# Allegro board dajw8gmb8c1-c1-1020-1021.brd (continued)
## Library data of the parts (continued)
D4 D7 D17 D18 D22 PD1 PQ2 PQ8 PQ12-PQ15 PQ18 PQ21 PQ22 PQ25 PQ27 PQ29 PQ33 PQ34 PQ37 PQ41 Q1 Q5-Q9 Q13 Q16 Q18 Q21 Q23 Q26 Q27 Q30 Q33 Q35 Q36 Q38 Q39 Q41-Q43 Q47 Q48 RTCD1 = UMT_213-3-1_3
EL1-EL4 EL6-EL8 = CHOKE-DLP11SN900HL2L-4P-1
EL5 L2 L8 L11 L19-L21 PR9 PR29 PR35 PR53 PR68 PR113 PR118 PR120 PR158 PR175 PR179 = RC0805
EL13 EL14 = CHOKE-NCCM20C900-TR-4P
ESD1-ESD6 PQ3 = TSOP6-2_8-95
EU1-EU3 = UDFN10-2_5X1-5
FAN1 FAN2 = 50271-0040N-V01-4P-L
G1 = SOLDERJUMPER-2
G2 L1 L3 L6 L7 L9 L10 L12-L15 L17 L18 L23-L25 PR3 PR4 PR6 PR10-PR12 PR15-PR21 PR23-PR28 PR31-PR33 PR36 PR37 PR40-PR49 PR52 PR54 PR56-PR59 PR64 PR65 PR67 PR69 PR71 PR74-PR82 PR85-PR87 PR89 PR91 PR93-PR97 PR99-PR102 PR104 PR106-PR112 PR115 PR116 PR119 PR121-PR127 PR129 PR133 PR134 PR136 PR139-PR141 PR143 PR146-PR151 PR159-PR162 PR164 PR166-PR174 PR177 PR180-PR182 PR188 PR190 PR191 PR202-PR207 PR424-PR428 PR432 PR434 R4-R18 R20-R25 R27 R28 R30-R36 R38-R49 R51-R53 R55 R57-R61 R63-R70 R72-R74 R76-R89 R91 R93 R94 R96-R102 R104-R108 R110-R117 R119-R127 R131 R132 R138-R142 R145-R147 R150 R151 R153 R155 R156 R158 R159 R161 R164-R168 R171 R173 R175 R176 R182 R186 R188 R195 R197 R199-R205 R207 R210 R211 R214 R217-R221 R223 R225 R227 R231-R233 R235 R236 R238 R239 R243-R246 R254 R255 R258-R264 R266-R270 R272 R274 R277 R279 R280 R282 R284-R287 R289-R292 R294-R314 R316-R323 R325-R362 R364-R378 R380-R386 R388 R389 R392 R393 R395-R414 R419-R422 R425 R429-R431 R435 R436 R439 R441-R448 R451 R452 R454 R456-R458 R460 R462-R464 R467-R469 R471 R473 R477-R483 R485-R489 R491 R500-R513 R517-R519 R524-R526 R528 RT1 RTCR1 = RC0402
H1 H2 = H-C59D59N
H3 H4 H6 = H-TC236BC315D98P2
H5 = H-TC315BC150D150PT
H7 = H-TC394BC315D130P2
H8 = INTEL-BKT-SHARK-ULT
H9 = H-TC315I190BC150D150PT
H10 H11 H13 = H-TC394BC315D138P2
H12 = H-TSBC315D98P2
H14 = H-TC276BC315D118P2
H17 = H-TC217BC141D141PT
HDMIF1 = F3_2X1_65-2_8
HDMIF2 HDMIF3 = F1_6X0_8-1_8
HE1 Q4 Q25 Q28 Q31 = SOT23_213-3_3-2
JDIM1 = DDR-DDRRK-20401-TP4B-204P-SMT
L4 L5 L32 = CHOKE-WCM2012-4P
L16 L26-L31 PR1 PR34 PR62 PR63 PR72 PR88 PR92 PR98 PR114 PR117 PR128 PR131 PR132 PR135 PR153 PR155 PR184 PR186 PR197-PR200 R1-R3 R37 R273 R453 = RC0603
L22 = L2_5X1_8-1_8-SMT
LED1-LED3 = LEDLTW-C191DS5
PC23-PC25 PC142 PC173 = CC7343-2_15H
PC99 PC141 PC149 PC168 PC172 PC175 = ECAP6D3S
PC100 = ECAP6_3X5_8-7_2
PL1 PL8-PL10 = CHOKE-MPL73-1R5
PL2 = L4_06X4_06-1_8
PL3 PL4 = CHOKE-PCMC063T-R82MN-4P-SMT
PL5 PL6 = CHOKE-ETQP4L
PL7 = CHOKE-MPLC0730L3R3
PQ1 PQ4 PQ7 = POWER-FDMC7678-5P
PQ5 PQ6 PQ16 PQ50 Q3 Q14 Q15 Q17 Q19 Q20 Q24 Q32 Q34 Q37 Q40 Q45 Q46 = SOT-363
PQ9 PQ10 PQ19 Q29 = SSOT6-2_8-95
PQ17 = SOT363-2_1-65-6P
PQ20 PQ23 PQ32 PQ35 PQ42-PQ46 PQ48 PQ49 = PG-TSDSON-8-8P-R
PQ24 PQ26 = SON8-4_5X3_5-5-9P-SMT
PQ28 PQ30 PQ36 PQ38-PQ40 PQ47 = SO-8FL-5P
PQ31 = SC74-2_8-95-6P
PQ901 = SOT23_123-2_37-1_9-1_11H
PR2 PR7 PR13 PR14 PR39 PR50 PR51 PR55 PR60 PR61 PR66 PR70 PR83 PR90 PR105 PR130 PR137 PR138 PR142 PR145 PR152 PR154 PR156 PR163 PR165 PR178 PR189 PR192 PR193 R19 R50 R56 R62 R71 R75 R95 R103 R109 R128 R134 R135 R137 R143 R148 R152 R154 R157 R160 R162 R169 R172 R177 R179 R181 R183 R189 R192 R194 R196 R198 R215 R216 R229 R230 R248 R249 R275 R288 R293 R324 R363 R379 R387 R390 R391 R394 R427 R433 R434 R450 R459 R461 R465 R466 R472 R475 R476 R484 SJ1 SJ2 = SHORT0402
PR8 PR194-PR196 = SHORT0201
PR22 PR103 R240 R283 = RC1206
PR38 = SHORT-1A
PR73 R26 R29 R149 R174 R224 R250 R315 R438 = SHORT0603
PR183 PR201 = RC3216-4P
PU1 PU4 PU5 = QFN24-4X4-5-25P
PU2 = SON8-2X2-5-9P
PU3 = PVQFN20-3_5X3_5-5-25P
PU6 = TQFN20-3X3-4-21P
PU7 = DFN10-3X3-5-11P-RT9296
PU8 = WQFN12-2X2-4-13P-SMT
PU9 = QFN32-4X4-4-42P-1H
PU11 = SOT23-6-4_2-95-6P
Q44 = SC70-2_1-65-6P
R54 R253 R276 R281 R449 R455 = SHORT0805
R440 = SHORT3720
RN1 = 8P4R-0402-SMT
RP1-RP23 = 4P2R-0404
RTCBT1 = 88266-0200-2P-L
TP1-TP9 TP17 TP20-TP29 TP35 TP38 TP40 TP41 TP43-TP54 TP56-TP62 TP64 TP65 TP67-TP70 = TP2650
TP10 TP15 TP16 TP18 TP19 TP30 TP32 TP63 = TP2050
TP11-TP13 TP31 TP33 TP34 TP36 TP37 = TP2675
U1 U15 = SSOP5-P-A-TOSHIBA-B
U2 = QFN40-5X5-4-50P-0_75H
U3 = TSSOP8-4_9-65
U4 U16 U17 = MSOP8-4_9-65
U5 = SOT353-1-2_125-65-5P
U6 U9 = QFN32-4X4-4-33P-0_9H
U7 = QFN40-5X5-4-41P-92HD99
U10 = QFN48-7X7-5-49P-ALC113-GR
U12 = TDFN8-3X3-65-9P-0_85H
U13 = BGA595-NVIDIA-N13P-GV2-S-A2
U14 = BGA1168-INTEL-HASWELL
U18 = QFN16-3X3-5-17P-WM9001
U19 = TRF-9_4-1_27-24P
U21 U24 = SOIC8-7_9-1_27-2_16H
U22 = SOT23-5
U23 = LQFP128-16X16-4
U25 = QFN48-7X7-5-58P-PS8620
VRAM1-VRAM4 = FBGA96-SAMSUNG-K4W2G1646B
Y1 Y4 = XTL-3_2X2_5-2_2X1_7-4P
Y2 = XTL-3_2X2_5-2_2X1_7
Y3 = XTL-3_2X1_5-2_5-0_8H

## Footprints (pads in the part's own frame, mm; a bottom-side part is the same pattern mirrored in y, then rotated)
4P2R-0404
  rect 0.33x0.762 smd: 1(-0.325,-0.5) 2(-0.325,0.5) 3(0.325,-0.5) 4(0.325,0.5)
8P4R-0402-SMT
  rect 0.406x0.61 smd: 1(-0.825,-0.45) 2(-0.825,0.45) 7(0.825,-0.45) 8(0.825,0.45)
  rect 0.254x0.61 smd: 3(-0.25,-0.45) 4(-0.25,0.45) 5(0.25,-0.45) 6(0.25,0.45)
50271-0040N-V01-4P-L
  rect 0.787x1.6 smd: 1(-1.875,2.9) 2(-0.625,2.9) 3(0.625,2.9) 4(1.875,2.9)
  rect 2.108x2.997 smd: 5(-4.425,0) 6(4.425,0)
50281-0060N-001-6P-L-SMT
  rect 0.787x2.007 smd: 1(-3.125,4.05) 2(-1.875,4.05) 3(-0.625,4.05) 4(0.625,4.05) 5(1.875,4.05) 6(3.125,4.05)
  rect 1.499x2.007 smd: 7(-5.075,0) 8(5.075,0)
50456-00841-001-8P-L
  round 1.702 hole 1.702 unplated: (-7.2,0) (7.2,0)
  round 1.346 hole 0.94: 1(-7,3.75) 2(-5,3.75) 3(-3,3.75) 4(-1,3.75) 5(1,3.75) 6(3,3.75) 7(5,3.75) 8(7,3.75)
  rect 1.6x2.489 smd: 9(-10.15,-4.45) 10(10.15,-4.45)
50503-0080N-001-8P-L
  rect 0.508x1.295 smd: 1(-3.5,1.4) 2(-2.5,1.4) 3(-1.5,1.4) 4(-0.5,1.4) 5(0.5,1.4) 6(1.5,1.4) 7(2.5,1.4) 8(3.5,1.4)
  rect 1.803x1.397 smd: 9(-5.65,-1.4) 10(5.65,-1.4)
88266-0200-2P-L
  rect 0.787x2.007 smd: 1(-0.625,2.725) 2(0.625,2.725)
  rect 2.007x2.489 smd: 3(-2.825,-1.325) 4(2.825,-1.325)
88513-0601-6P-L-SMT
  rect 0.508x1.6 smd: 1(-2.5,2.95) 2(-1.5,2.95) 3(-0.5,2.95) 4(0.5,2.95) 5(1.5,2.95) 6(2.5,2.95)
  rect 1.803x1.397 smd: 7(-4.65,0) 8(4.65,0)
BGA595-NVIDIA-N13P-GV2-S-A2
  round 0.381 smd: A2(-9.9,10.7) A3(-9.1,10.7) A4(-8.3,10.7) A6(-6.6,10.7) A7(-5.8,10.7) A9(-4.12,10.7) A10(-3.32,10.7) A12(-1.64,10.7) A13(-0.84,10.7) A15(0.84,10.7) A16(1.64,10.7) A18(3.32,10.7) A19(4.12,10.7) A21(5.8,10.7) A22(6.6,10.7) A24(8.3,10.7) A25(9.1,10.7) A26(9.9,10.7) AA1(-10.7,-5.8) AA2(-9.9,-5.8) AA3(-9.1,-5.8) AA4(-8.3,-5.8) AA5(-7.5,-5.8) AA6(-6.66,-5.8) AA7(-5.8,-5.8) AA8(-4.96,-5.8) AA9(-4.12,-5.86) AA10(-3.32,-5.86) AA12(-1.64,-5.86) AA13(-0.84,-5.86) AA14(0,-5.86) AA15(0.84,-5.86) AA16(1.64,-5.86) AA18(3.32,-5.86) AA19(4.12,-5.86) AA20(4.96,-5.8) AA21(5.8,-5.8) AA22(6.66,-5.8) AA23(7.5,-5.8) AA24(8.3,-5.8) AA25(9.1,-5.8) AA26(9.9,-5.8) AA27(10.7,-5.8) AB1(-10.7,-6.6) AB2(-9.9,-6.6) AB3(-9.1,-6.6) AB4(-8.3,-6.6) AB5(-7.5,-6.6) AB6(-6.6,-6.6) AB7(-5.8,-6.66) AB8(-4.96,-6.66) AB9(-4.12,-6.66) AB10(-3.32,-6.66) AB11(-2.48,-6.66) AB12(-1.64,-6.66) AB13(-0.84,-6.66) AB14(0,-6.66) AB15(0.84,-6.66) AB16(1.64,-6.66) AB17(2.48,-6.66) AB18(3.32,-6.66) AB19(4.12,-6.66) AB20(4.96,-6.66) AB21(5.8,-6.66) AB22(6.6,-6.6) AB23(7.5,-6.6) AB24(8.3,-6.6) AB25(9.1,-6.6) AB26(9.9,-6.6) AB27(10.7,-6.6) AC2(-9.9,-7.45) AC3(-9.1,-7.45) AC4(-8.3,-7.45) AC5(-7.45,-7.45) AC6(-6.6,-7.5) AC7(-5.8,-7.5) AC8(-4.96,-7.5) AC9(-4.12,-7.5) AC10(-3.32,-7.5) AC11(-2.48,-7.5) AC12(-1.64,-7.5) AC13(-0.84,-7.5) AC14(0,-7.5) AC15(0.84,-7.5) AC16(1.64,-7.5) AC17(2.48,-7.5) AC18(3.32,-7.5) AC19(4.12,-7.5) AC20(4.96,-7.5) AC21(5.8,-7.5) AC22(6.6,-7.5) AC23(7.45,-7.45) AC24(8.3,-7.45) AC25(9.1,-7.45) AC26(9.9,-7.45) AD1(-10.7,-8.3) AD2(-9.9,-8.3) AD3(-9.1,-8.3) AD4(-8.3,-8.3) AD5(-7.45,-8.3) AD6(-6.6,-8.3) AD7(-5.8,-8.3) AD8(-4.96,-8.3) AD9(-4.12,-8.3) AD10(-3.32,-8.3) AD11(-2.48,-8.3) AD12(-1.64,-8.3) AD13(-0.84,-8.3) AD14(0,-8.3) AD15(0.84,-8.3) AD16(1.64,-8.3) AD17(2.48,-8.3) AD18(3.32,-8.3) AD19(4.12,-8.3) AD20(4.96,-8.3) AD21(5.8,-8.3) AD22(6.6,-8.3) AD23(7.45,-8.3) AD24(8.3,-8.3) AD25(9.1,-8.3) AD26(9.9,-8.3) AD27(10.7,-8.3) AE1(-10.7,-9.1) AE2(-9.9,-9.1) AE3(-9.1,-9.1) AE4(-8.3,-9.1) AE5(-7.45,-9.1) AE6(-6.6,-9.1) AE7(-5.8,-9.1) AE8(-4.96,-9.1) AE9(-4.12,-9.1) AE10(-3.32,-9.1) AE11(-2.48,-9.1) AE12(-1.64,-9.1) AE13(-0.84,-9.1) AE14(0,-9.1) AE15(0.84,-9.1) AE16(1.64,-9.1) AE17(2.48,-9.1) AE18(3.32,-9.1) AE19(4.12,-9.1) AE20(4.96,-9.1) AE21(5.8,-9.1) AE22(6.6,-9.1) AE23(7.45,-9.1) AE24(8.3,-9.1) AE25(9.1,-9.1) AE26(9.9,-9.1) AE27(10.7,-9.1) AF1(-10.7,-9.9) AF2(-9.9,-9.9) AF3(-9.1,-9.9) AF4(-8.3,-9.9) AF5(-7.45,-9.9) AF6(-6.6,-9.9) AF7(-5.8,-9.9) AF8(-4.96,-9.9) AF9(-4.12,-9.9) AF10(-3.32,-9.9) AF11(-2.48,-9.9) AF12(-1.64,-9.9) AF13(-0.84,-9.9) AF14(0,-9.9) AF15(0.84,-9.9) AF16(1.64,-9.9) AF17(2.48,-9.9) AF18(3.32,-9.9) AF19(4.12,-9.9) AF20(4.96,-9.9) AF21(5.8,-9.9) AF22(6.6,-9.9) AF23(7.45,-9.9) AF24(8.3,-9.9) AF25(9.1,-9.9) AF26(9.9,-9.9) AF27(10.7,-9.9) AG2(-9.9,-10.7) AG3(-9.1,-10.7) AG4(-8.3,-10.7) AG6(-6.6,-10.7) AG7(-5.8,-10.7) AG9(-4.12,-10.7) AG10(-3.32,-10.7) AG12(-1.64,-10.7) AG13(-0.84,-10.7) AG15(0.84,-10.7) AG16(1.64,-10.7) AG18(3.32,-10.7) AG19(4.12,-10.7) AG21(5.8,-10.7) AG22(6.6,-10.7) AG24(8.3,-10.7) AG25(9.1,-10.7) AG26(9.9,-10.7) B1(-10.7,9.9) B2(-9.9,9.9) B3(-9.1,9.9) B4(-8.3,9.9) B5(-7.45,9.9) B6(-6.6,9.9) B7(-5.8,9.9) B8(-4.96,9.9) B9(-4.12,9.9) B10(-3.32,9.9) B11(-2.48,9.9) B12(-1.64,9.9) B13(-0.84,9.9) B14(0,9.9) B15(0.84,9.9) B16(1.64,9.9) B17(2.48,9.9) B18(3.32,9.9) B19(4.12,9.9) B20(4.96,9.9) B21(5.8,9.9) B22(6.6,9.9) B23(7.45,9.9) B24(8.3,9.9) B25(9.1,9.9) B26(9.9,9.9) B27(10.7,9.9) C1(-10.7,9.1) C2(-9.9,9.1) C3(-9.1,9.1) C4(-8.3,9.1) C5(-7.45,9.1) C6(-6.6,9.1) C7(-5.8,9.1) C8(-4.96,9.1) C9(-4.12,9.1) C10(-3.32,9.1) C11(-2.48,9.1) C12(-1.64,9.1) C13(-0.84,9.1) C14(0,9.1) C15(0.84,9.1) C16(1.64,9.1) C17(2.48,9.1) C18(3.32,9.1) C19(4.12,9.1) C20(4.96,9.1) C21(5.8,9.1) C22(6.6,9.1) C23(7.45,9.1) C24(8.3,9.1) C25(9.1,9.1) C26(9.9,9.1) C27(10.7,9.1) D1(-10.7,8.3) D2(-9.9,8.3) D3(-9.1,8.3) D4(-8.3,8.3) D5(-7.45,8.3) D6(-6.6,8.3) D7(-5.8,8.3) D8(-4.96,8.3) D9(-4.12,8.3) D10(-3.32,8.3) D11(-2.48,8.3) D12(-1.64,8.3) D13(-0.84,8.3) D14(0,8.3) D15(0.84,8.3) D16(1.64,8.3) D17(2.48,8.3) D18(3.32,8.3) D19(4.12,8.3) D20(4.96,8.3) D21(5.8,8.3) D22(6.6,8.3) D23(7.45,8.3) D24(8.3,8.3) D25(9.1,8.3) D26(9.9,8.3) D27(10.7,8.3) E2(-9.9,7.45) E3(-9.1,7.45) E4(-8.3,7.45) E5(-7.45,7.45) E6(-6.6,7.5) E7(-5.8,7.5) E8(-4.96,7.5) E9(-4.12,7.5) E10(-3.32,7.5) E11(-2.48,7.5) E12(-1.64,7.5) E13(-0.84,7.5) E14(0,7.5) E15(0.84,7.5) E16(1.64,7.5) E17(2.48,7.5) E18(3.32,7.5) E19(4.12,7.5) E20(4.96,7.5) E21(5.8,7.5) E22(6.6,7.5) E23(7.45,7.45) E24(8.3,7.45) E25(9.1,7.45) E26(9.9,7.45) F1(-10.7,6.6) F2(-9.9,6.6) F3(-9.1,6.6) F4(-8.3,6.6) F5(-7.5,6.6) F6(-6.6,6.6) F7(-5.8,6.66) F8(-4.96,6.66) F9(-4.12,6.66) F10(-3.32,6.66) F11(-2.48,6.66) F12(-1.64,6.66) F13(-0.84,6.66) F14(0,6.66) F15(0.84,6.66) F16(1.64,6.66) F17(2.48,6.66) F18(3.32,6.66) F19(4.12,6.66) F20(4.96,6.66) F21(5.8,6.66) F22(6.6,6.6) F23(7.5,6.6) F24(8.3,6.6) F25(9.1,6.6) F26(9.9,6.6) F27(10.7,6.6) G1(-10.7,5.8) G2(-9.9,5.8) G3(-9.1,5.8) G4(-8.3,5.8) G5(-7.5,5.8) G6(-6.66,5.8) G7(-5.8,5.8) G8(-4.96,5.8) G9(-4.12,5.86) G10(-3.32,5.86) G12(-1.64,5.86) G13(-0.84,5.86) G14(0,5.86) G15(0.84,5.86) G16(1.64,5.86) G18(3.32,5.86) G19(4.12,5.86) G20(4.96,5.8) G21(5.8,5.8) G22(6.66,5.8) G23(7.5,5.8) G24(8.3,5.8) G25(9.1,5.8) G26(9.9,5.8) G27(10.7,5.8) H2(-9.9,4.96) H3(-9.1,4.96) H4(-8.3,4.96) H5(-7.5,4.96) H6(-6.66,4.96) H22(6.66,4.96) H23(7.5,4.96) H24(8.3,4.96) H25(9.1,4.96) H26(9.9,4.96) J1(-10.7,4.12) J2(-9.9,4.12) J3(-9.1,4.12) J4(-8.3,4.12) J5(-7.5,4.12) J6(-6.66,4.12) J7(-5.86,4.12) J21(5.86,4.12) J22(6.66,4.12) J23(7.5,4.12) J24(8.3,4.12) J25(9.1,4.12) J26(9.9,4.12) J27(10.7,4.12) K1(-10.7,3.32) K2(-9.9,3.32) K3(-9.1,3.32) K4(-8.3,3.32) K5(-7.5,3.32) K6(-6.66,3.32) K7(-5.86,3.32) K21(5.86,3.32) K22(6.66,3.32) K23(7.5,3.32) K24(8.3,3.32) K25(9.1,3.32) K26(9.9,3.32) K27(10.7,3.32) L2(-9.9,2.48) L3(-9.1,2.48) L4(-8.3,2.48) L5(-7.5,2.48) L6(-6.66,2.48) L22(6.66,2.48) L23(7.5,2.48) L24(8.3,2.48) L25(9.1,2.48) L26(9.9,2.48) M1(-10.7,1.64) M2(-9.9,1.64) M3(-9.1,1.64) M4(-8.3,1.64) M5(-7.5,1.64) M6(-6.66,1.64) M7(-5.86,1.64) M21(5.86,1.64) M22(6.66,1.64) M23(7.5,1.64) M24(8.3,1.64) M25(9.1,1.64) M26(9.9,1.64) M27(10.7,1.64) N1(-10.7,0.84) N2(-9.9,0.84) N3(-9.1,0.84) N4(-8.3,0.84) N5(-7.5,0.84) N6(-6.66,0.84) N7(-5.86,0.84) N21(5.86,0.84) N22(6.66,0.84) N23(7.5,0.84) N24(8.3,0.84) N25(9.1,0.84) N26(9.9,0.84) N27(10.7,0.84) P2(-9.9,0) P3(-9.1,0) P4(-8.3,0) P5(-7.5,0) P6(-6.66,0) P22(6.66,0) P23(7.5,0) P24(8.3,0) P25(9.1,0) P26(9.9,0) R1(-10.7,-0.84) R2(-9.9,-0.84) R3(-9.1,-0.84) R4(-8.3,-0.84) R5(-7.5,-0.84) R6(-6.66,-0.84) R7(-5.86,-0.84) R21(5.86,-0.84) R22(6.66,-0.84) R23(7.5,-0.84) R24(8.3,-0.84) R25(9.1,-0.84) R26(9.9,-0.84) R27(10.7,-0.84) T1(-10.7,-1.64) T2(-9.9,-1.64) T3(-9.1,-1.64) T4(-8.3,-1.64) T5(-7.5,-1.64) T6(-6.66,-1.64) T7(-5.86,-1.64) T21(5.86,-1.64) T22(6.66,-1.64) T23(7.5,-1.64) T24(8.3,-1.64) T25(9.1,-1.64) T26(9.9,-1.64) T27(10.7,-1.64) U2(-9.9,-2.48) U3(-9.1,-2.48) U4(-8.3,-2.48) U5(-7.5,-2.48) U6(-6.66,-2.48) U22(6.66,-2.48) U23(7.5,-2.48) U24(8.3,-2.48) U25(9.1,-2.48) U26(9.9,-2.48) V1(-10.7,-3.32) V2(-9.9,-3.32) V3(-9.1,-3.32) V4(-8.3,-3.32) V5(-7.5,-3.32) V6(-6.66,-3.32) V7(-5.86,-3.32) V21(5.86,-3.32) V22(6.66,-3.32) V23(7.5,-3.32) V24(8.3,-3.32) V25(9.1,-3.32) V26(9.9,-3.32) V27(10.7,-3.32) W1(-10.7,-4.12) W2(-9.9,-4.12) W3(-9.1,-4.12) W4(-8.3,-4.12) W5(-7.5,-4.12) W6(-6.66,-4.12) W7(-5.86,-4.12) W21(5.86,-4.12) W22(6.66,-4.12) W23(7.5,-4.12) W24(8.3,-4.12) W25(9.1,-4.12) W26(9.9,-4.12) W27(10.7,-4.12) Y2(-9.9,-4.96) Y3(-9.1,-4.96) Y4(-8.3,-4.96) Y5(-7.5,-4.96) Y6(-6.66,-4.96) Y22(6.66,-4.96) Y23(7.5,-4.96) Y24(8.3,-4.96) Y25(9.1,-4.96) Y26(9.9,-4.96)
  round 0.4 smd: K10(-4,4) K11(-3,4) K12(-2,4) K13(-1,4) K14(0,4) K15(1,4) K16(2,4) K17(3,4) K18(4,4) L10(-4,3) L11(-3,3) L12(-2,3) L13(-1,3) L14(0,3) L15(1,3) L16(2,3) L17(3,3) L18(4,3) M10(-4,2) M11(-3,2) M12(-2,2) M13(-1,2) M14(0,2) M15(1,2) M16(2,2) M17(3,2) M18(4,2) N10(-4,1) N11(-3,1) N12(-2,1) N13(-1,1) N14(0,1) N15(1,1) N16(2,1) N17(3,1) N18(4,1) P10(-4,0) P11(-3,0) P12(-2,0) P13(-1,0) P14(0,0) P15(1,0) P16(2,0) P17(3,0) P18(4,0) R10(-4,-1) R11(-3,-1) R12(-2,-1) R13(-1,-1) R14(0,-1) R15(1,-1) R16(2,-1) R17(3,-1) R18(4,-1) T10(-4,-2) T11(-3,-2) T12(-2,-2) T13(-1,-2) T14(0,-2) T15(1,-2) T16(2,-2) T17(3,-2) T18(4,-2) U10(-4,-3) U11(-3,-3) U12(-2,-3) U13(-1,-3) U14(0,-3) U15(1,-3) U16(2,-3) U17(3,-3) U18(4,-3) V10(-4,-4) V11(-3,-4) V12(-2,-4) V13(-1,-4) V14(0,-4) V15(1,-4) V16(2,-4) V17(3,-4) V18(4,-4)
BGA1168-INTEL-HASWELL
  round 0.508 smd: A3(18.177,-11.314) A62(-18.722,-11.314) AW1(19.314,10.727) AW63(-19.314,10.743) AY2(18.771,11.314) AY62(-18.748,11.314) B2(18.806,-10.806) B63(-19.314,-10.722) C1(19.314,-10.177)
  round 0.381 smd: A4(17.421,-11.314) A5(16.76,-11.314) A6(15.564,-11.314) A59(-16.586,-11.314) A60(-17.412,-11.314) A61(-18.072,-11.314) AA9(14.282,0.262) AA21(7.627,0.175) AA23(6.199,0.175) AA58(-16.063,0.015) AB10(13.838,0.738) AB20(8.135,0.582) AB21(7.627,0.988) AB22(6.707,0.582) AB23(6.199,0.988) AB57(-15.743,0.666) AC9(14.282,1.215) AC20(8.135,1.394) AC22(6.707,1.394) AC58(-16.063,1.316) AD10(13.838,1.691) AD21(7.627,1.801) AD23(6.199,1.801) AD57(-15.743,1.966) AE9(14.282,2.167) AE10(13.838,2.643) AE20(8.135,2.207) AE21(7.627,2.614) AE22(6.707,2.207) AE23(6.199,2.614) AE58(-16.063,2.616) AF9(14.282,3.12) AF11(13.255,2.968) AF12(12.442,2.968) AF14(11.63,2.968) AF15(10.817,2.968) AF17(10.004,2.968) AF18(9.191,2.968) AF20(8.378,2.968) AF22(6.707,3.02) AG10(13.662,3.476) AG11(12.849,3.476) AG13(12.036,3.476) AG14(11.223,3.476) AG16(10.41,3.476) AG17(9.598,3.476) AG19(8.785,3.476) AG20(7.972,3.476) AG23(6.199,3.426) AG57(-15.743,3.267) AG58(-16.377,3.695) AH22(6.707,3.833) AH24(5.394,3.975) AH26(4.094,3.975) AH28(2.793,3.975) AH30(1.493,3.975) AH32(0.192,3.975) AH34(-1.108,3.975) AH36(-2.409,3.975) AH38(-3.709,3.975) AH40(-5.01,3.975) AH42(-6.31,3.975) AH44(-7.611,3.975) AH46(-8.911,3.975) AH49(-10.212,3.975) AH51(-11.512,3.975) AH53(-12.813,3.975) AH55(-14.113,3.975) AH57(-15.413,3.975) AJ23(6.199,4.239) AJ25(4.744,4.3) AJ27(3.443,4.3) AJ29(2.143,4.3) AJ31(0.843,4.3) AJ33(-0.458,4.3) AJ35(-1.758,4.3) AJ37(-3.059,4.3) AJ39(-4.359,4.3) AJ41(-5.66,4.3) AJ43(-6.96,4.3) AJ45(-8.261,4.3) AJ47(-9.561,4.3) AJ50(-10.862,4.3) AJ52(-12.162,4.3) AJ54(-13.463,4.3) AJ56(-14.763,4.3) AJ58(-16.064,4.3) AT1(19.314,8.683) AT63(-19.314,8.533) AU1(19.314,9.343) AU63(-19.314,9.359) AV1(19.314,10.004) AV2(18.654,9.993) AV62(-18.664,10.004) AV63(-19.314,10.019) AW2(18.654,10.654) AW3(17.993,10.654) AW61(-18.014,10.664) AW62(-18.664,10.664) AY3(18.047,11.314) AY4(17.387,11.314) AY5(16.726,11.314) AY59(-16.774,11.314) AY60(-17.434,11.314) AY61(-18.095,11.314) B3(18.056,-10.664) B61(-18.001,-10.654) B62(-18.664,-10.59) C2(18.664,-10.056) C62(-18.664,-9.93) C63(-19.314,-9.998) D1(19.314,-9.453) D63(-19.314,-9.338) E1(19.314,-8.792) E23(5.981,-8.713) E25(4.6,-8.713) E27(3.474,-8.713) E29(2.093,-8.713) E31(0.966,-8.713) E33(-0.415,-8.713) E35(-1.541,-8.713) E37(-2.922,-8.713) E39(-4.049,-8.713) E41(-5.43,-8.713) E43(-6.556,-8.713) E45(-7.937,-8.713) E47(-9.064,-8.713) E49(-10.444,-8.713) E51(-11.571,-8.713) E53(-12.952,-8.713) E55(-14.079,-8.713) E57(-15.459,-8.713) E63(-19.314,-8.667) F1(19.314,-7.878) F22(6.597,-8.256) F24(5.291,-8.188) F26(4.037,-8.188) F28(2.783,-8.188) F30(1.53,-8.188) F32(0.276,-8.188) F34(-0.978,-8.188) F36(-2.232,-8.188) F38(-3.485,-8.188) F40(-4.739,-8.188) F42(-5.993,-8.188) F44(-7.247,-8.188) F46(-8.5,-8.188) F48(-9.754,-8.188) F50(-11.008,-8.188) F52(-12.262,-8.188) F54(-13.515,-8.188) F56(-14.769,-8.188) F58(-16.063,-8.188) G22(6.707,-7.546) G23(5.981,-7.863) G25(4.6,-7.863) G27(3.474,-7.863) G29(2.093,-7.863) G31(0.966,-7.863) G33(-0.415,-7.863) G35(-1.541,-7.863) G37(-2.922,-7.863) G39(-4.049,-7.863) G41(-5.43,-7.863) G43(-6.556,-7.863) G45(-7.937,-7.863) G47(-9.064,-7.863) G49(-10.444,-7.863) G51(-11.571,-7.863) G53(-12.952,-7.863) G55(-14.079,-7.863) G57(-15.459,-7.863) H22(6.707,-6.734) H23(6.199,-7.14) H57(-15.743,-7.213) J22(6.707,-5.921) J23(6.199,-6.327) J58(-16.063,-6.487) K9(14.282,-5.453) K10(13.379,-5.614) K12(12.426,-5.614) K14(11.474,-5.614) K16(10.521,-5.614) K18(9.569,-5.614) K19(8.616,-5.614) K21(7.664,-5.614) K23(6.199,-5.514) K57(-15.743,-5.837) L10(13.838,-4.977) L11(12.902,-5.17) L13(11.95,-5.17) L15(10.997,-5.17) L17(10.045,-5.17) L18(9.092,-5.17) L20(8.135,-5.108) L22(6.707,-5.108) L58(-16.063,-5.186) M9(14.282,-4.5) M20(8.135,-4.295) M21(7.627,-4.702) M22(6.707,-4.295) M23(6.199,-4.702) M57(-15.743,-4.536) N10(13.838,-4.024) N21(7.627,-3.889) N23(6.199,-3.889) N58(-16.063,-3.886) P9(14.282,-3.548) P20(8.135,-3.482) P22(6.707,-3.482) P57(-15.743,-3.236) R10(13.838,-3.072) R20(8.135,-2.67) R21(7.627,-3.076) R22(6.707,-2.67) R23(6.199,-3.076) T9(14.282,-2.595) T21(7.627,-2.263) T23(6.199,-2.263) T58(-16.063,-2.585) U9(14.282,-1.643) U10(13.838,-2.119) U20(8.135,-1.857) U22(6.707,-1.857) U57(-15.743,-1.935) V10(13.838,-1.167) V21(7.627,-1.45) V23(6.199,-1.45) V58(-16.063,-1.285) W9(14.282,-0.69) W20(8.135,-1.044) W21(7.627,-0.638) W22(6.707,-1.044) W23(6.199,-0.638) W57(-15.743,-0.635) Y10(13.838,-0.214) Y20(8.135,-0.231) Y22(6.707,-0.231)
  round 0.305 smd: A8(14.776,-11.314) A9(13.862,-11.314) A11(12.948,-11.314) A12(12.198,-11.314) A14(11.284,-11.314) A15(10.37,-11.314) A17(9.62,-11.314) A18(8.706,-11.314) A20(7.791,-11.314) A21(7.042,-11.314) A23(6.128,-11.314) A24(5.291,-10.989) A25(4.6,-11.314) A27(3.474,-11.314) A28(2.783,-10.989) A29(2.093,-11.314) A31(0.966,-11.314) A32(0.276,-10.989) A33(-0.415,-11.314) A35(-1.541,-11.314) A36(-2.232,-10.989) A37(-2.922,-11.314) A39(-4.049,-11.314) A40(-4.739,-10.989) A41(-5.43,-11.314) A43(-6.556,-11.314) A44(-7.247,-10.989) A45(-7.937,-11.314) A47(-9.064,-11.314) A48(-9.754,-10.989) A49(-10.444,-11.314) A51(-11.571,-11.314) A52(-12.262,-10.989) A53(-12.952,-11.314) A55(-14.079,-11.314) A56(-14.769,-10.989) A57(-15.459,-11.314) AA1(19.314,0.402) AA2(18.664,0.402) AA3(18.014,0.364) AA4(17.363,0.364) AA59(-16.713,0.324) AA60(-17.363,0.324) AA61(-18.014,0.324) AA62(-18.664,0.362) AA63(-19.314,0.362) AB5(16.678,0.738) AB6(16.027,0.738) AB7(15.377,0.738) AB8(14.727,0.738) AC1(19.314,1.152) AC2(18.664,1.152) AC3(18.014,1.19) AC4(17.363,1.19) AC59(-16.713,1.15) AC60(-17.363,1.15) AC61(-18.014,1.15) AC62(-18.664,1.112) AC63(-19.314,1.112) AD1(19.314,1.901) AD2(18.664,1.901) AD3(18.014,1.863) AD4(17.363,1.863) AD5(16.678,1.691) AD6(16.027,1.691) AD7(15.377,1.691) AD8(14.727,1.691) AD59(-16.713,1.823) AD60(-17.363,1.823) AD61(-18.014,1.823) AD62(-18.664,1.861) AD63(-19.314,1.861) AE5(16.678,2.643) AE6(16.027,2.643) AE7(15.377,2.643) AE8(14.727,2.643) AE59(-16.713,2.648) AE60(-17.363,2.648) AE61(-18.014,2.648) AE62(-18.664,2.61) AE63(-19.314,2.61) AF1(19.314,2.65) AF2(18.664,2.65) AF3(18.014,2.688) AF4(17.363,2.688) AG1(19.314,3.4) AG2(18.664,3.4) AG3(18.014,3.361) AG4(17.363,3.361) AG5(16.678,3.596) AG6(16.027,3.596) AG7(15.377,3.596) AG8(14.727,3.596) AG21(7.359,3.807) AG60(-17.038,3.288) AG61(-17.689,3.288) AG62(-18.339,3.288) AG63(-18.989,3.288) AH1(19.314,4.149) AH2(18.664,4.149) AH3(18.014,4.187) AH4(17.363,4.187) AH10(13.662,4.162) AH11(12.849,4.162) AH13(12.036,4.162) AH14(11.223,4.162) AH16(10.41,4.162) AH17(9.598,4.162) AH19(8.785,4.162) AH20(7.972,4.162) AH60(-17.363,3.964) AH61(-18.014,3.964) AH62(-18.664,3.964) AH63(-19.314,3.964) AJ5(16.678,4.548) AJ6(16.027,4.548) AJ7(15.377,4.548) AJ8(14.727,4.548) AJ10(13.662,4.812) AJ11(12.849,4.812) AJ13(12.036,4.812) AJ14(11.223,4.812) AJ60(-17.038,4.64) AJ61(-17.689,4.64) AJ62(-18.339,4.64) AJ63(-18.989,4.64) AK1(19.314,4.898) AK2(18.664,4.898) AK3(18.014,4.86) AK4(17.363,4.86) AK8(15.011,5.137) AK18(9.466,4.952) AK20(8.513,4.952) AK21(7.561,4.952) AK60(-17.363,5.209) AK61(-18.014,5.209) AK62(-18.664,5.315) AK63(-19.314,5.315) AL1(19.314,5.647) AL2(18.664,5.647) AL3(18.014,5.686) AL4(17.363,5.686) AL5(16.413,5.462) AL7(15.575,5.462) AL8(15.011,5.787) AL10(13.657,5.462) AL11(13.093,5.787) AL13(11.738,5.462) AL15(11.174,5.787) AL17(10.092,5.268) AL18(9.466,5.602) AL20(8.513,5.602) AL21(7.561,5.602) AL22(6.608,5.602) AL23(5.786,5.602) AL25(4.81,5.602) AL26(3.858,5.602) AL28(2.905,5.602) AL29(1.953,5.602) AL31(1.054,5.277) AL32(0.49,5.602) AL33(-0.412,5.602) AL35(-1.415,5.602) AL36(-2.266,5.602) AL38(-3.32,5.602) AL39(-4.228,5.277) AL40(-4.817,5.602) AL42(-5.63,5.602) AL43(-6.582,5.602) AL45(-7.56,5.602) AL46(-8.487,5.602) AL48(-9.542,5.602) AL49(-10.443,5.602) AL51(-11.447,5.602) AL52(-12.269,5.602) AL54(-13.295,5.602) AL55(-14.248,5.602) AL57(-15.195,5.602) AL58(-16.094,5.602) AL60(-17.038,5.855) AL61(-17.689,5.855) AM1(19.314,6.397) AM2(18.664,6.397) AM3(18.014,6.359) AM4(17.363,6.359) AM5(16.413,6.112) AM7(15.575,6.112) AM8(15.011,6.437) AM10(13.657,6.112) AM11(13.093,6.437) AM13(11.738,6.112) AM15(11.174,6.437) AM17(10.092,5.919) AM18(9.466,6.252) AM20(8.513,6.252) AM21(7.561,6.252) AM22(6.608,6.252) AM23(5.786,6.252) AM25(4.81,6.252) AM26(3.858,6.252) AM28(2.905,6.252) AM29(1.953,6.252) AM31(1.054,5.927) AM32(0.49,6.252) AM33(-0.412,6.252) AM35(-1.415,6.252) AM36(-2.266,6.252) AM38(-3.32,6.252) AM40(-4.817,6.252) AM42(-5.63,6.252) AM43(-6.582,6.252) AM45(-7.56,6.252) AM46(-8.487,6.252) AM48(-9.542,6.252) AM49(-10.443,6.252) AM51(-11.447,6.252) AM52(-12.269,6.252) AM54(-13.295,6.252) AM55(-14.248,6.252) AM57(-15.195,6.252) AM58(-16.094,6.252) AM60(-17.363,6.501) AM61(-18.014,6.501) AM62(-18.664,6.395) AM63(-19.314,6.395) AN1(19.314,7.146) AN2(18.664,7.146) AN3(18.014,7.184) AN4(17.363,7.184) AN5(16.413,6.762) AN7(15.575,6.762) AN8(15.011,7.088) AN10(13.657,6.762) AN11(13.093,7.088) AN13(11.738,6.762) AN15(11.174,7.088) AN17(10.092,6.569) AN18(9.466,6.903) AN20(8.513,6.903) AN21(7.561,6.903) AN22(6.608,6.903) AN23(5.786,6.903) AN25(4.81,6.903) AN26(3.858,6.903) AN28(2.905,6.903) AN29(1.953,6.903) AN31(1.054,6.578) AN32(0.49,6.903) AN33(-0.412,6.903) AN35(-1.415,6.903) AN36(-2.266,6.903) AN38(-3.32,6.903) AN39(-4.228,6.578) AN40(-4.817,6.903) AN42(-5.63,6.903) AN43(-6.582,6.903) AN45(-7.56,6.903) AN46(-8.487,6.903) AN48(-9.542,6.903) AN49(-10.443,6.903) AN51(-11.447,6.903) AN52(-12.269,6.903) AN54(-13.295,6.903) AN55(-14.248,6.903) AN57(-15.195,6.903) AN58(-16.094,6.903) AN60(-17.038,7.07) AN61(-17.689,7.07) AN62(-18.339,7.07) AN63(-18.989,7.07) AP1(19.314,7.895) AP2(18.664,7.895) AP3(18.014,7.857) AP4(17.363,7.857) AP5(16.413,7.413) AP7(15.575,7.413) AP8(15.011,7.738) AP10(13.657,7.413) AP11(13.093,7.738) AP13(11.738,7.413) AP15(11.174,7.738) AP17(10.092,7.219) AP18(9.466,7.553) AP20(8.513,7.553) AP21(7.561,7.553) AP22(6.608,7.553) AP23(5.786,7.553) AP25(4.81,7.553) AP26(3.858,7.553) AP28(2.905,7.553) AP29(1.953,7.553) AP31(1.054,7.228) AP32(0.49,7.553) AP33(-0.412,7.553) AP35(-1.415,7.553) AP36(-2.266,7.553) AP38(-3.32,7.553) AP39(-4.228,7.228) AP40(-4.817,7.553) AP42(-5.63,7.553) AP43(-6.582,7.553) AP45(-7.56,7.553) AP46(-8.487,7.553) AP48(-9.542,7.553) AP49(-10.443,7.553) AP51(-11.447,7.553) AP52(-12.269,7.553) AP54(-13.295,7.553) AP55(-14.248,7.553) AP57(-15.195,7.553) AP58(-16.094,7.553) AP60(-17.363,7.746) AP61(-18.014,7.746) AP62(-18.664,7.746) AP63(-19.314,7.746) AR5(16.413,8.063) AR7(15.575,8.063) AR8(15.011,8.388) AR10(13.657,8.063) AR11(13.093,8.388) AR13(11.738,8.063) AR15(11.174,8.388) AR17(10.092,7.869) AR18(9.466,8.203) AR20(8.513,8.203) AR21(7.561,8.203) AR22(6.608,8.203) AR23(5.786,8.203) AR25(4.81,8.203) AR26(3.858,8.203) AR28(2.905,8.203) AR29(1.953,8.203) AR31(1.054,7.878) AR32(0.49,8.203) AR33(-0.412,8.203) AR35(-1.415,8.203) AR36(-2.266,8.203) AR38(-3.32,8.203) AR39(-4.228,7.878) AR40(-4.817,8.203) AR42(-5.63,8.203) AR43(-6.582,8.203) AR45(-7.56,8.203) AR46(-8.487,8.203) AR48(-9.542,8.203) AR49(-10.443,8.203) AR51(-11.447,8.203) AR52(-12.269,8.203) AR54(-13.295,8.203) AR55(-14.248,8.203) AR57(-15.195,8.203) AR58(-16.094,8.203) AT2(18.664,8.645) AT3(18.014,8.683) AT4(17.363,8.683) AT5(16.413,8.713) AT7(15.575,8.713) AT10(13.657,8.713) AT13(11.738,8.713) AT35(-1.122,8.905) AT37(-2.697,8.905) AT40(-4.272,8.905) AT42(-5.847,8.905) AT43(-7.422,8.905) AT46(-8.996,8.905) AT49(-10.597,8.933) AT61(-17.689,8.32) AT62(-18.498,8.376) AU2(18.659,9.333) AU3(17.999,9.333) AU4(17.338,9.333) AU6(15.977,9.363) AU7(15.151,9.363) AU8(14.478,9.363) AU10(13.653,9.363) AU11(12.98,9.363) AU12(12.154,9.363) AU14(11.481,9.363) AU15(10.656,9.363) AU16(10.092,9.038) AU17(9.454,9.363) AU18(8.778,9.038) AU19(8.21,9.363) AU20(7.563,9.038) AU21(6.917,9.363) AU22(6.348,9.038) AU23(5.672,9.363) AU24(4.996,9.038) AU25(4.321,9.363) AU26(3.645,9.038) AU27(3.076,9.363) AU28(2.43,9.038) AU29(1.783,9.363) AU30(1.214,9.038) AU31(0.539,9.363) AU33(-0.058,9.016) AU34(-0.66,9.363) AU35(-1.585,9.363) AU36(-2.235,9.363) AU37(-3.16,9.363) AU39(-3.81,9.363) AU40(-4.734,9.363) AU41(-5.385,9.363) AU42(-6.309,9.363) AU43(-6.959,9.363) AU44(-7.884,9.363) AU46(-8.534,9.363) AU47(-9.459,9.363) AU49(-10.109,9.363) AU50(-11.086,9.363) AU51(-11.666,9.038) AU52(-12.342,9.363) AU53(-13.017,9.038) AU54(-13.586,9.363) AU55(-14.233,9.038) AU56(-14.879,9.363) AU57(-15.448,9.038) AU58(-16.124,9.363) AU59(-16.688,9.038) AU60(-17.251,9.363) AU61(-17.963,9.087) AU62(-18.664,9.349) AV3(17.993,9.993) AV4(17.338,9.993) AV5(16.65,10.014) AV6(15.977,10.014) AV7(15.151,10.014) AV8(14.478,10.014) AV10(13.653,10.014) AV11(12.98,10.014) AV12(12.154,10.014) AV14(11.481,10.014) AV15(10.656,10.014) AV16(10.092,9.689) AV17(9.454,10.014) AV18(8.778,9.689) AV19(8.21,10.014) AV20(7.563,9.689) AV21(6.917,10.014) AV22(6.348,9.689) AV23(5.672,10.014) AV24(4.996,9.689) AV25(4.321,10.014) AV26(3.645,9.689) AV27(3.076,10.014) AV28(2.43,9.689) AV29(1.783,10.014) AV30(1.214,9.689) AV31(0.539,10.014) AV33(-0.086,9.689) AV34(-0.71,10.014) AV35(-1.535,10.014) AV36(-2.284,10.014) AV37(-3.11,10.014) AV39(-3.859,10.014) AV40(-4.685,10.014) AV41(-5.434,10.014) AV42(-6.26,10.014) AV43(-7.009,10.014) AV44(-7.834,10.014) AV46(-8.584,10.014) AV47(-9.409,10.014) AV49(-10.158,10.014) AV50(-10.984,10.014) AV51(-11.666,9.689) AV52(-12.342,10.014) AV53(-13.017,9.689) AV54(-13.586,10.014) AV55(-14.233,9.689) AV56(-14.879,10.014) AV57(-15.448,9.689) AV58(-16.124,10.014) AV59(-16.688,9.689) AV60(-17.251,10.014) AV61(-17.988,9.737) AW4(17.338,10.654) AW5(16.688,10.664) AW6(15.939,10.664) AW7(15.189,10.664) AW8(14.44,10.664) AW10(13.691,10.664) AW11(12.942,10.664) AW12(12.192,10.664) AW14(11.443,10.664) AW15(10.694,10.664) AW16(10.092,10.339) AW17(9.454,10.664) AW18(8.778,10.339) AW19(8.103,10.664) AW21(7.023,10.664) AW22(6.348,10.339) AW23(5.672,10.664) AW24(4.996,10.339) AW25(4.321,10.664) AW26(3.645,10.339) AW27(2.97,10.664) AW29(1.89,10.664) AW30(1.214,10.339) AW31(0.539,10.664) AW33(-0.137,10.339) AW34(-0.71,10.664) AW35(-1.535,10.664) AW36(-2.284,10.664) AW37(-3.11,10.664) AW39(-3.859,10.664) AW40(-4.685,10.664) AW41(-5.434,10.664) AW42(-6.26,10.664) AW43(-7.009,10.664) AW44(-7.834,10.664) AW46(-8.584,10.664) AW47(-9.409,10.664) AW49(-10.158,10.664) AW50(-10.984,10.664) AW51(-11.666,10.339) AW52(-12.342,10.664) AW53(-13.017,10.339) AW54(-13.693,10.664) AW56(-14.772,10.664) AW57(-15.448,10.339) AW58(-16.124,10.664) AW59(-16.688,10.339) AW60(-17.251,10.664) AY6(15.939,11.314) AY7(15.189,11.314) AY8(14.44,11.314) AY10(13.691,11.314) AY11(12.942,11.314) AY12(12.192,11.314) AY14(11.443,11.314) AY15(10.694,11.314) AY16(10.13,10.989) AY17(9.454,11.314) AY18(8.778,10.989) AY19(8.103,11.314) AY21(7.023,11.314) AY22(6.348,10.989) AY23(5.672,11.314) AY24(4.996,10.989) AY25(4.321,11.314) AY26(3.645,10.989) AY27(2.97,11.314) AY29(1.89,11.314) AY30(1.214,10.989) AY31(0.539,11.314) AY33(-0.137,10.989) AY34(-0.71,11.314) AY35(-1.535,11.314) AY36(-2.284,11.314) AY37(-3.11,11.314) AY39(-3.859,11.314) AY40(-4.685,11.314) AY41(-5.434,11.314) AY42(-6.26,11.314) AY43(-7.009,11.314) AY44(-7.834,11.314) AY46(-8.584,11.314) AY47(-9.409,11.314) AY49(-10.158,11.314) AY50(-10.984,11.314) AY51(-11.666,10.989) AY52(-12.342,11.314) AY53(-13.017,10.989) AY54(-13.693,11.314) AY56(-14.772,11.314) AY57(-15.448,10.989) AY58(-16.124,11.314) B4(17.393,-10.664) B5(16.176,-10.672) B6(15.196,-10.672) B8(14.423,-10.672) B9(13.598,-10.672) B11(12.617,-10.672) B12(11.845,-10.672) B14(11.02,-10.672) B15(10.039,-10.672) B17(9.267,-10.672) B18(8.442,-10.672) B20(7.461,-10.672) B21(7.042,-10.118) B22(6.689,-10.672) B23(5.864,-10.672) B24(5.291,-10.339) B25(4.6,-10.664) B26(4.037,-10.339) B27(3.474,-10.664) B28(2.783,-10.339) B29(2.093,-10.664) B30(1.53,-10.339) B31(0.966,-10.664) B32(0.276,-10.339) B33(-0.415,-10.664) B34(-0.978,-10.339) B35(-1.541,-10.664) B36(-2.232,-10.339) B37(-2.922,-10.664) B38(-3.485,-10.339) B39(-4.049,-10.664) B40(-4.739,-10.339) B41(-5.43,-10.664) B42(-5.993,-10.339) B43(-6.556,-10.664) B44(-7.247,-10.339) B45(-7.937,-10.664) B46(-8.5,-10.339) B47(-9.064,-10.664) B48(-9.754,-10.339) B49(-10.444,-10.664) B50(-11.008,-10.339) B51(-11.571,-10.664) B52(-12.262,-10.339) B53(-12.952,-10.664) B54(-13.515,-10.339) B55(-14.079,-10.664) B56(-14.769,-10.339) B57(-15.459,-10.664) B58(-16.023,-10.339) B59(-16.586,-10.664) B60(-17.351,-10.654) C3(18.012,-10.012) C4(17.196,-10.042) C5(16.542,-10.118) C6(15.538,-10.118) C8(14.776,-10.118) C9(13.964,-10.118) C11(12.96,-10.118) C12(12.198,-10.118) C14(11.386,-10.118) C15(10.382,-10.118) C17(9.62,-10.118) C18(8.807,-10.118) C20(7.804,-10.118) C21(7.423,-9.529) C22(6.636,-9.529) C23(6.229,-10.118) C24(5.263,-9.282) C25(4.6,-10.014) C26(4.037,-9.689) C27(3.474,-10.014) C28(2.756,-9.282) C29(2.093,-10.014) C30(1.53,-9.689) C31(0.966,-10.014) C32(0.248,-9.282) C33(-0.415,-10.014) C34(-0.978,-9.689) C35(-1.541,-10.014) C36(-2.259,-9.282) C37(-2.922,-10.014) C38(-3.485,-9.689) C39(-4.049,-10.014) C40(-4.767,-9.282) C41(-5.43,-10.014) C42(-5.993,-9.689) C43(-6.556,-10.014) C44(-7.274,-9.282) C45(-7.937,-10.014) C46(-8.5,-9.689) C47(-9.064,-10.014) C48(-9.756,-9.282) C49(-10.444,-10.014) C50(-11.008,-9.689) C51(-11.571,-10.014) C52(-12.264,-9.323) C53(-12.952,-10.014) C54(-13.515,-9.689) C55(-14.079,-10.014) C56(-14.771,-9.323) C57(-15.459,-10.014) C58(-16.023,-9.689) C59(-16.586,-10.014) C61(-17.689,-10.077) D2(18.664,-9.24) D3(18.014,-9.278) D5(16.636,-9.472) D6(15.945,-9.529) D8(15.157,-9.529) D9(14.37,-9.529) D11(13.462,-9.529) D12(12.579,-9.529) D14(11.792,-9.529) D15(10.884,-9.529) D17(10.001,-9.529) D18(9.214,-9.529) D20(8.306,-9.529) D21(7.079,-8.891) D23(5.937,-9.529) D25(4.6,-9.363) D26(4.037,-9.038) D27(3.474,-9.363) D29(2.093,-9.363) D30(1.53,-9.038) D31(0.966,-9.363) D33(-0.415,-9.363) D34(-0.978,-9.038) D35(-1.541,-9.363) D37(-2.922,-9.363) D38(-3.485,-9.038) D39(-4.049,-9.363) D41(-5.43,-9.363) D42(-5.993,-9.038) D43(-6.556,-9.363) D45(-7.937,-9.363) D46(-8.5,-9.038) D47(-9.064,-9.363) D49(-10.444,-9.363) D50(-11.008,-9.038) D51(-11.571,-9.363) D53(-12.952,-9.363) D54(-13.515,-9.038) D55(-14.079,-9.363) D57(-15.459,-9.363) D58(-16.023,-9.038) D59(-16.586,-9.363) D60(-17.363,-9.513) D61(-18.014,-9.513) D62(-18.664,-9.28) E2(18.664,-8.589) E3(18.014,-8.627) E4(17.363,-8.627) E5(16.712,-8.695) E6(15.76,-8.695) E8(14.807,-8.695) E10(13.855,-8.695) E11(12.902,-8.695) E13(11.95,-8.695) E15(10.997,-8.695) E17(10.045,-8.695) E18(9.092,-8.695) E20(8.14,-8.695) E59(-16.713,-8.667) E60(-17.363,-8.667) E61(-18.014,-8.667) E62(-18.664,-8.629) F2(18.664,-7.84) F3(18.014,-7.802) F4(17.363,-7.802) F5(16.712,-8.045) F6(15.76,-8.045) F8(14.807,-8.045) F10(13.855,-8.045) F11(12.902,-8.045) F13(11.95,-8.045) F15(10.997,-8.045) F17(10.045,-8.045) F18(9.092,-8.045) F20(8.14,-8.045) F59(-16.713,-7.842) F60(-17.363,-7.842) F61(-18.014,-7.842) F62(-18.664,-7.88) F63(-19.314,-7.88) G1(19.314,-7.091) G2(18.664,-7.091) G3(18.014,-7.129) G4(17.363,-7.129) G5(16.712,-7.395) G6(15.76,-7.395) G8(14.807,-7.395) G10(13.855,-7.395) G11(12.902,-7.395) G13(11.95,-7.395) G15(10.997,-7.395) G17(10.045,-7.395) G18(9.092,-7.395) G20(8.14,-7.395) H5(16.712,-6.745) H6(15.76,-6.745) H8(14.807,-6.745) H10(13.855,-6.745) H11(12.902,-6.745) H13(11.95,-6.745) H15(10.997,-6.745) H17(10.045,-6.745) H18(9.092,-6.745) H20(8.14,-6.745) H59(-16.713,-7.169) H60(-17.363,-7.169) H61(-18.014,-7.169) H62(-18.664,-7.131) H63(-19.314,-7.131) J1(19.314,-6.341) J2(18.664,-6.341) J3(18.014,-6.303) J4(17.363,-6.303) J5(16.687,-6.094) J6(15.747,-6.094) J8(14.807,-6.094) J10(13.855,-6.094) J11(12.902,-6.094) J13(11.95,-6.094) J15(10.997,-6.094) J17(10.045,-6.094) J18(9.092,-6.094) J20(8.14,-6.094) J21(7.219,-6.328) J59(-16.713,-6.343) J60(-17.363,-6.343) J61(-18.014,-6.343) J62(-18.664,-6.381) J63(-19.314,-6.381) K1(19.314,-5.592) K2(18.664,-5.592) K3(18.014,-5.63) K4(17.363,-5.63) K59(-16.713,-5.67) K60(-17.363,-5.67) K61(-18.014,-5.67) K62(-18.664,-5.632) K63(-19.314,-5.632) L1(19.314,-4.843) L2(18.664,-4.843) L3(18.014,-4.805) L4(17.363,-4.805) L5(16.678,-4.977) L6(16.027,-4.977) L7(15.377,-4.977) L8(14.727,-4.977) L59(-16.713,-4.845) L60(-17.363,-4.845) L61(-18.014,-4.845) L62(-18.664,-4.883) L63(-19.314,-4.883) N1(19.314,-4.093) N2(18.664,-4.093) N3(18.014,-4.132) N4(17.363,-4.132) N5(16.678,-4.024) N6(16.027,-4.024) N7(15.377,-4.024) N8(14.727,-4.024) N59(-16.713,-4.172) N60(-17.363,-4.172) N61(-18.014,-4.172) N62(-18.664,-4.134) N63(-19.314,-4.134) P1(19.314,-3.344) P2(18.664,-3.344) P3(18.014,-3.306) P4(17.363,-3.306) P59(-16.713,-3.346) P60(-17.363,-3.346) P61(-18.014,-3.346) P62(-18.664,-3.384) P63(-19.314,-3.384) R5(16.678,-3.072) R6(16.027,-3.072) R7(15.377,-3.072) R8(14.727,-3.072) T1(19.314,-2.595) T2(18.664,-2.595) T3(18.014,-2.633) T4(17.363,-2.633) T59(-16.713,-2.673) T60(-17.363,-2.673) T61(-18.014,-2.673) T62(-18.664,-2.635) T63(-19.314,-2.635) U1(19.314,-1.846) U2(18.664,-1.846) U3(18.014,-1.807) U4(17.363,-1.807) U5(16.678,-2.119) U6(16.027,-2.119) U7(15.377,-2.119) U8(14.727,-2.119) U59(-16.713,-1.848) U60(-17.363,-1.848) U61(-18.014,-1.848) U62(-18.664,-1.886) U63(-19.314,-1.886) V1(19.314,-1.096) V2(18.664,-1.096) V3(18.014,-1.134) V4(17.363,-1.134) V5(16.678,-1.167) V6(16.027,-1.167) V7(15.377,-1.167) V8(14.727,-1.167) V59(-16.713,-1.174) V60(-17.363,-1.174) V61(-18.014,-1.174) V62(-18.664,-1.136) V63(-19.314,-1.136) Y1(19.314,-0.347) Y2(18.664,-0.347) Y3(18.014,-0.309) Y4(17.363,-0.309) Y5(16.678,-0.214) Y6(16.027,-0.214) Y7(15.377,-0.214) Y8(14.727,-0.214) Y59(-16.713,-0.349) Y60(-17.363,-0.349) Y61(-18.014,-0.349) Y62(-18.664,-0.387) Y63(-19.314,-0.387)
  round 0.33 smd: AK22(6.659,4.952) AK23(5.786,4.952) AK25(4.81,4.952) AK26(3.858,4.952) AK28(2.905,4.952) AK29(2.004,4.952) AK32(0.49,4.952) AK33(-0.412,4.952) AK35(-1.415,4.952) AK36(-2.266,4.952) AK38(-3.295,4.952) AK40(-4.792,4.952) AK42(-5.63,4.952) AK43(-6.582,4.952) AK45(-7.56,4.952) AK46(-8.462,4.952) AK48(-9.516,4.952) AK49(-10.418,4.952) AK51(-11.421,4.952) AK52(-12.269,4.952) AK54(-13.295,4.952) AK55(-14.248,4.952) AK57(-15.195,4.952) AK58(-16.094,4.952)
BL135H-32RLA-TAND-32P-L-SMT
  rect 0.508x1.295 smd: 1(-15.5,3.25) 2(-14.5,3.25) 3(-13.5,3.25) 4(-12.5,3.25) 5(-11.5,3.25) 6(-10.5,3.25) 7(-9.5,3.25) 8(-8.5,3.25) 9(-7.5,3.25) 10(-6.5,3.25) 11(-5.5,3.25) 12(-4.5,3.25) 13(-3.5,3.25) 14(-2.5,3.25) 15(-1.5,3.25) 16(-0.5,3.25) 17(0.5,3.25) 18(1.5,3.25) 19(2.5,3.25) 20(3.5,3.25) 21(4.5,3.25) 22(5.5,3.25) 23(6.5,3.25) 24(7.5,3.25) 25(8.5,3.25) 26(9.5,3.25) 27(10.5,3.25) 28(11.5,3.25) 29(12.5,3.25) 30(13.5,3.25) 31(14.5,3.25) 32(15.5,3.25)
  rect 1.803x2.21 smd: 33(-17.9,0) 34(17.9,0)
CC0402
  custom 0.12x0.12 smd: 1(0.39,0) 2(-0.39,0)
CC0603
  rect 0.813x0.711 smd: 1(0.737,0) 2(-0.737,0)
CC0805
  rect 0.94x1.346 smd: 1(0.895,0) 2(-0.895,0)
CC1808
  rect 2.159x2.286 smd: 1(-2.349,0) 2(2.349,0)
CC3528
  rect 2.032x2.413 smd: 1(1.6,0) 2(-1.6,0)
CC7343-2_15H
  rect 2.057x2.896 smd: 1(-3.075,0) 2(3.075,0)
CHOKE-DLP11SN900HL2L-4P-1
  rect 0.711x0.305 smd: 1(-0.625,0.275) 2(0.625,0.275) 3(0.625,-0.275) 4(-0.625,-0.275)
CHOKE-ETQP4L
  rect 2.896x4.293 smd: 1(-4.216,0) 2(4.216,0)
CHOKE-MPL73-1R5
  rect 1.676x3.404 smd: 1(-2.843,0) 2(2.843,0)
CHOKE-MPLC0730L3R3
  rect 2.007x3.505 smd: 1(-2.95,0) 2(2.95,0)
CHOKE-NCCM20C900-TR-4P
  rect 0.889x0.406 smd: 1(-0.85,0.4) 2(0.85,0.4) 3(0.85,-0.4) 4(-0.85,-0.4)
CHOKE-PCMC063T-R82MN-4P-SMT
  custom 0.591x0.591 smd: 1(-3.596,0) 2(3.596,0)
  rect 1.473x0.305 smd: 3(-2.452,0) 4(2.452,0)
CHOKE-WCM2012-4P
  rect 0.889x0.406 smd: 1(-0.85,0.4) 2(0.85,0.4) 3(0.85,-0.4) 4(-0.85,-0.4)
DCJK-2DC3074-000111F-2P
  round 2.159 hole 1.448: 1(0,10.95)
  oval 1.6x2.438 hole 0.889x1.753: 2(-2.98,10.95)
  oval 1.6x2.743 hole 0.889x2.057: 3(-5.75,0) 4(5.75,0)
DDR-DDRRK-20401-TP4B-204P-SMT
  round 1.194 hole 1.194 unplated: (-33.4,0)
  round 1.702 hole 1.702 unplated: (33.4,0)
  rect 0.356x2.007 smd: 1(31.65,4.1) 2(31.35,-4.1) 3(31.05,4.1) 4(30.75,-4.1) 5(30.45,4.1) 6(30.15,-4.1) 7(29.85,4.1) 8(29.55,-4.1) 9(29.25,4.1) 10(28.95,-4.1) 11(28.65,4.1) 12(28.35,-4.1) 13(28.05,4.1) 14(27.75,-4.1) 15(27.45,4.1) 16(27.15,-4.1) 17(26.85,4.1) 18(26.55,-4.1) 19(26.25,4.1) 20(25.95,-4.1) 21(25.65,4.1) 22(25.35,-4.1) 23(25.05,4.1) 24(24.75,-4.1) 25(24.45,4.1) 26(24.15,-4.1) 27(23.85,4.1) 28(23.55,-4.1) 29(23.25,4.1) 30(22.95,-4.1) 31(22.65,4.1) 32(22.35,-4.1) 33(22.05,4.1) 34(21.75,-4.1) 35(21.45,4.1) 36(21.15,-4.1) 37(20.85,4.1) 38(20.55,-4.1) 39(20.25,4.1) 40(19.95,-4.1) 41(19.65,4.1) 42(19.35,-4.1) 43(19.05,4.1) 44(18.75,-4.1) 45(18.45,4.1) 46(18.15,-4.1) 47(17.85,4.1) 48(17.55,-4.1) 49(17.25,4.1) 50(16.95,-4.1) 51(16.65,4.1) 52(16.35,-4.1) 53(16.05,4.1) 54(15.75,-4.1) 55(15.45,4.1) 56(15.15,-4.1) 57(14.85,4.1) 58(14.55,-4.1) 59(14.25,4.1) 60(13.95,-4.1) 61(13.65,4.1) 62(13.35,-4.1) 63(13.05,4.1) 64(12.75,-4.1) 65(12.45,4.1) 66(12.15,-4.1) 67(11.85,4.1) 68(11.55,-4.1) 69(11.25,4.1) 70(10.95,-4.1) 71(10.65,4.1) 72(10.35,-4.1) 73(7.65,4.1) 74(7.35,-4.1) 75(7.05,4.1) 76(6.75,-4.1) 77(6.45,4.1) 78(6.15,-4.1) 79(5.85,4.1) 80(5.55,-4.1) 81(5.25,4.1) 82(4.95,-4.1) 83(4.65,4.1) 84(4.35,-4.1) 85(4.05,4.1) 86(3.75,-4.1) 87(3.45,4.1) 88(3.15,-4.1) 89(2.85,4.1) 90(2.55,-4.1) 91(2.25,4.1) 92(1.95,-4.1) 93(1.65,4.1) 94(1.35,-4.1) 95(1.05,4.1) 96(0.75,-4.1) 97(0.45,4.1) 98(0.15,-4.1) 99(-0.15,4.1) 100(-0.45,-4.1) 101(-0.75,4.1) 102(-1.05,-4.1) 103(-1.35,4.1) 104(-1.65,-4.1) 105(-1.95,4.1) 106(-2.25,-4.1) 107(-2.55,4.1) 108(-2.85,-4.1) 109(-3.15,4.1) 110(-3.45,-4.1) 111(-3.75,4.1) 112(-4.05,-4.1) 113(-4.35,4.1) 114(-4.65,-4.1) 115(-4.95,4.1) 116(-5.25,-4.1) 117(-5.55,4.1) 118(-5.85,-4.1) 119(-6.15,4.1) 120(-6.45,-4.1) 121(-6.75,4.1) 122(-7.05,-4.1) 123(-7.35,4.1) 124(-7.65,-4.1) 125(-7.95,4.1) 126(-8.25,-4.1) 127(-8.55,4.1) 128(-8.85,-4.1) 129(-9.15,4.1) 130(-9.45,-4.1) 131(-9.75,4.1) 132(-10.05,-4.1) 133(-10.35,4.1) 134(-10.65,-4.1) 135(-10.95,4.1) 136(-11.25,-4.1) 137(-11.55,4.1) 138(-11.85,-4.1) 139(-12.15,4.1) 140(-12.45,-4.1) 141(-12.75,4.1) 142(-13.05,-4.1) 143(-13.35,4.1) 144(-13.65,-4.1) 145(-13.95,4.1) 146(-14.25,-4.1) 147(-14.55,4.1) 148(-14.85,-4.1) 149(-15.15,4.1) 150(-15.45,-4.1) 151(-15.75,4.1) 152(-16.05,-4.1) 153(-16.35,4.1) 154(-16.65,-4.1) 155(-16.95,4.1) 156(-17.25,-4.1) 157(-17.55,4.1) 158(-17.85,-4.1) 159(-18.15,4.1) 160(-18.45,-4.1) 161(-18.75,4.1) 162(-19.05,-4.1) 163(-19.35,4.1) 164(-19.65,-4.1) 165(-19.95,4.1) 166(-20.25,-4.1) 167(-20.55,4.1) 168(-20.85,-4.1) 169(-21.15,4.1) 170(-21.45,-4.1) 171(-21.75,4.1) 172(-22.05,-4.1) 173(-22.35,4.1) 174(-22.65,-4.1) 175(-22.95,4.1) 176(-23.25,-4.1) 177(-23.55,4.1) 178(-23.85,-4.1) 179(-24.15,4.1) 180(-24.45,-4.1) 181(-24.75,4.1) 182(-25.05,-4.1) 183(-25.35,4.1) 184(-25.65,-4.1) 185(-25.95,4.1) 186(-26.25,-4.1) 187(-26.55,4.1) 188(-26.85,-4.1) 189(-27.15,4.1) 190(-27.45,-4.1) 191(-27.75,4.1) 192(-28.05,-4.1) 193(-28.35,4.1) 194(-28.65,-4.1) 195(-28.95,4.1) 196(-29.25,-4.1) 197(-29.55,4.1) 198(-29.85,-4.1) 199(-30.15,4.1) 200(-30.45,-4.1) 201(-30.75,4.1) 202(-31.05,-4.1) 203(-31.35,4.1) 204(-31.65,-4.1)
  rect 4.496x4.597 smd: 207(32.55,12) 208(-32.55,12)
DFN10-3X3-5-11P-RT9296
  rect 0.305x0.991 smd: 1(-1,-1.6) 2(-0.5,-1.6) 3(0,-1.6) 4(0.5,-1.6) 5(1,-1.6) 6(1,1.6) 7(0.5,1.6) 8(0,1.6) 9(-0.5,1.6) 10(-1,1.6)
  rect 2.464x1.626 smd: 11(0,0)
DSM
  rect 1.016x0.508 smd: 1(-1.3,0) 2(1.321,0)
DSMV
  rect 1.016x0.762 smd: 1(-1.27,0) 2(1.27,0)
ECAP6_3X5_8-7_2
  rect 3.505x1.6 smd: 1(2.35,0) 2(-2.35,0)
ECAP6D3S
  rect 3.099x0.991 smd: 1(2.565,0) 2(-2.565,0)
F1_6X0_8-1_8
  rect 0.991x0.991 smd: 1(-0.9,0) 2(0.9,0)
F3_2X1_65-2_8
  rect 0.991x1.803 smd: 1(-1.4,0) 2(1.4,0)
FBGA96-SAMSUNG-K4W2G1646B
  round 0.356 smd: A1(-3.2,6) A2(-2.4,6) A3(-1.6,6) A7(1.6,6) A8(2.4,6) A9(3.2,6) B1(-3.2,5.2) B2(-2.4,5.2) B3(-1.6,5.2) B7(1.6,5.2) B8(2.4,5.2) B9(3.2,5.2) C1(-3.2,4.4) C2(-2.4,4.4) C3(-1.6,4.4) C7(1.6,4.4) C8(2.4,4.4) C9(3.2,4.4) D1(-3.2,3.6) D2(-2.4,3.6) D3(-1.6,3.6) D7(1.6,3.6) D8(2.4,3.6) D9(3.2,3.6) E1(-3.2,2.8) E2(-2.4,2.8) E3(-1.6,2.8) E7(1.6,2.8) E8(2.4,2.8) E9(3.2,2.8) F1(-3.2,2) F2(-2.4,2) F3(-1.6,2) F7(1.6,2) F8(2.4,2) F9(3.2,2) G1(-3.2,1.2) G2(-2.4,1.2) G3(-1.6,1.2) G7(1.6,1.2) G8(2.4,1.2) G9(3.2,1.2) H1(-3.2,0.4) H2(-2.4,0.4) H3(-1.6,0.4) H7(1.6,0.4) H8(2.4,0.4) H9(3.2,0.4) J1(-3.2,-0.4) J2(-2.4,-0.4) J3(-1.6,-0.4) J7(1.6,-0.4) J8(2.4,-0.4) J9(3.2,-0.4) K1(-3.2,-1.2) K2(-2.4,-1.2) K3(-1.6,-1.2) K7(1.6,-1.2) K8(2.4,-1.2) K9(3.2,-1.2) L1(-3.2,-2) L2(-2.4,-2) L3(-1.6,-2) L7(1.6,-2) L8(2.4,-2) L9(3.2,-2) M1(-3.2,-2.8) M2(-2.4,-2.8) M3(-1.6,-2.8) M7(1.6,-2.8) M8(2.4,-2.8) M9(3.2,-2.8) N1(-3.2,-3.6) N2(-2.4,-3.6) N3(-1.6,-3.6) N7(1.6,-3.6) N8(2.4,-3.6) N9(3.2,-3.6) P1(-3.2,-4.4) P2(-2.4,-4.4) P3(-1.6,-4.4) P7(1.6,-4.4) P8(2.4,-4.4) P9(3.2,-4.4) R1(-3.2,-5.2) R2(-2.4,-5.2) R3(-1.6,-5.2) R7(1.6,-5.2) R8(2.4,-5.2) R9(3.2,-5.2) T1(-3.2,-6) T2(-2.4,-6) T3(-1.6,-6) T7(1.6,-6) T8(2.4,-6) T9(3.2,-6)
GS12203-1011-9F-20P-R
  round 0.838 hole 0.838 unplated: (-5.8,0) (5.8,0)
  rect 0.254x1.143 smd: 1(4.75,2.325) 2(4.25,2.325) 3(3.75,2.325) 4(3.25,2.325) 5(2.75,2.325) 6(2.25,2.325) 7(1.75,2.325) 8(1.25,2.325) 9(0.75,2.325) 10(0.25,2.325) 11(-0.25,2.325) 12(-0.75,2.325) 13(-1.25,2.325) 14(-1.75,2.325) 15(-2.25,2.325) 16(-2.75,2.325) 17(-3.25,2.325) 18(-3.75,2.325) 19(-4.25,2.325) 20(-4.75,2.325)
  rect 1.295x1.397 smd: 21(5.8,2.2) 22(-5.8,2.2) 23(5.8,-1.8) 24(-5.8,-1.8)
GS12301-1011A-9F-30P-L-SMT
  round 0.991 hole 0.991 unplated: (-8,0) (8,0)
  rect 0.254x1.143 smd: 1(-7.25,2.125) 2(-6.75,2.125) 3(-6.25,2.125) 4(-5.75,2.125) 5(-5.25,2.125) 6(-4.75,2.125) 7(-4.25,2.125) 8(-3.75,2.125) 9(-3.25,2.125) 10(-2.75,2.125) 11(-2.25,2.125) 12(-1.75,2.125) 13(-1.25,2.125) 14(-0.75,2.125) 15(-0.25,2.125) 16(0.25,2.125) 17(0.75,2.125) 18(1.25,2.125) 19(1.75,2.125) 20(2.25,2.125) 21(2.75,2.125) 22(3.25,2.125) 23(3.75,2.125) 24(4.25,2.125) 25(4.75,2.125) 26(5.25,2.125) 27(5.75,2.125) 28(6.25,2.125) 29(6.75,2.125) 30(7.25,2.125)
  rect 1.499x2.997 smd: 31(-10.15,0.05) 32(10.15,0.05)
  rect 2.794x1.499 smd: 33(-5.7,-2.45) 34(5.7,-2.45)
H-C59D59N
  round 1.499 hole 1.499 unplated: (0,0)
H-TC217BC141D141PT
  round 3.581 hole 3.581: 1(0,0)
H-TC236BC315D98P2
  round 5.994 hole 2.489: 1(0,0)
H-TC276BC315D118P2
  custom 2.238x2.238 hole 2.997: 1(0,0)
H-TC315BC150D150PT
  round 8.001 hole 3.81: 1(0,0)
H-TC315I190BC150D150PT
  round 8.001 hole 3.81: 1(0,0)
H-TC394BC315D130P2
  round 10.008 hole 3.302: 1(0,0)
H-TC394BC315D138P2
  round 10.008 hole 3.505: 1(0,0)
H-TSBC315D98P2
  custom 2.125x2.125 hole 2.489: 1(0,0)
HDMI-2HE1608-000111F-19P-LDV
  round 0.813 hole 0.559: 1(-4.5,6.65) 2(-4,8.2) 3(-3.5,6.65) 4(-3,8.2) 5(-2.5,6.65) 6(-2,8.2) 7(-1.5,6.65) 8(-1,8.2) 9(-0.5,6.65) 10(0,8.2) 11(0.5,6.65) 12(1,8.2) 13(1.5,6.65) 14(2,8.2) 15(2.5,6.65) 16(3,8.2) 17(3.5,6.65) 18(4,8.2) 19(4.5,6.65)
  oval 1.803x2.794 hole 0.787x1.803: 20(-9.25,0) 21(9.25,0)
  oval 1.803x3.607 hole 0.787x2.591: 22(-7.25,7.6) 23(7.25,7.6)
INTEL-BKT-SHARK-ULT
  round 7.188 hole 3.759: 1(-26,14) 2(26,14)
  round 7.188 hole 3.607: 3(26,-14)
  round 7.01 hole 3.81x3.607: 4(-26,-14)
L2_5X1_8-1_8-SMT
  rect 1.194x2.007 smd: 1(-1.2,0) 2(1.2,0)
L4_06X4_06-1_8
  rect 1.499x2.388 smd: 1(-1.85,0) 2(1.85,0)
LEDLTW-C191DS5
  rect 0.787x0.787 smd: 1(-0.75,0) 2(0.75,0)
LQFP128-16X16-4
  rect 0.203x1.499 smd: 1(-6.2,-7.85) 2(-5.8,-7.85) 3(-5.4,-7.85) 4(-5,-7.85) 5(-4.6,-7.85) 6(-4.2,-7.85) 7(-3.8,-7.85) 8(-3.4,-7.85) 9(-3,-7.85) 10(-2.6,-7.85) 11(-2.2,-7.85) 12(-1.8,-7.85) 13(-1.4,-7.85) 14(-1,-7.85) 15(-0.6,-7.85) 16(-0.2,-7.85) 17(0.2,-7.85) 18(0.6,-7.85) 19(1,-7.85) 20(1.4,-7.85) 21(1.8,-7.85) 22(2.2,-7.85) 23(2.6,-7.85) 24(3,-7.85) 25(3.4,-7.85) 26(3.8,-7.85) 27(4.2,-7.85) 28(4.6,-7.85) 29(5,-7.85) 30(5.4,-7.85) 31(5.8,-7.85) 32(6.2,-7.85) 65(6.2,7.85) 66(5.8,7.85) 67(5.4,7.85) 68(5,7.85) 69(4.6,7.85) 70(4.2,7.85) 71(3.8,7.85) 72(3.4,7.85) 73(3,7.85) 74(2.6,7.85) 75(2.2,7.85) 76(1.8,7.85) 77(1.4,7.85) 78(1,7.85) 79(0.6,7.85) 80(0.2,7.85) 81(-0.2,7.85) 82(-0.6,7.85) 83(-1,7.85) 84(-1.4,7.85) 85(-1.8,7.85) 86(-2.2,7.85) 87(-2.6,7.85) 88(-3,7.85) 89(-3.4,7.85) 90(-3.8,7.85) 91(-4.2,7.85) 92(-4.6,7.85) 93(-5,7.85) 94(-5.4,7.85) 95(-5.8,7.85) 96(-6.2,7.85)
  rect 1.499x0.203 smd: 33(7.85,-6.2) 34(7.85,-5.8) 35(7.85,-5.4) 36(7.85,-5) 37(7.85,-4.6) 38(7.85,-4.2) 39(7.85,-3.8) 40(7.85,-3.4) 41(7.85,-3) 42(7.85,-2.6) 43(7.85,-2.2) 44(7.85,-1.8) 45(7.85,-1.4) 46(7.85,-1) 47(7.85,-0.6) 48(7.85,-0.2) 49(7.85,0.2) 50(7.85,0.6) 51(7.85,1) 52(7.85,1.4) 53(7.85,1.8) 54(7.85,2.2) 55(7.85,2.6) 56(7.85,3) 57(7.85,3.4) 58(7.85,3.8) 59(7.85,4.2) 60(7.85,4.6) 61(7.85,5) 62(7.85,5.4) 63(7.85,5.8) 64(7.85,6.2) 97(-7.85,6.2) 98(-7.85,5.8) 99(-7.85,5.4) 100(-7.85,5) 101(-7.85,4.6) 102(-7.85,4.2) 103(-7.85,3.8) 104(-7.85,3.4) 105(-7.85,3) 106(-7.85,2.6) 107(-7.85,2.2) 108(-7.85,1.8) 109(-7.85,1.4) 110(-7.85,1) 111(-7.85,0.6) 112(-7.85,0.2) 113(-7.85,-0.2) 114(-7.85,-0.6) 115(-7.85,-1) 116(-7.85,-1.4) 117(-7.85,-1.8) 118(-7.85,-2.2) 119(-7.85,-2.6) 120(-7.85,-3) 121(-7.85,-3.4) 122(-7.85,-3.8) 123(-7.85,-4.2) 124(-7.85,-4.6) 125(-7.85,-5) 126(-7.85,-5.4) 127(-7.85,-5.8) 128(-7.85,-6.2)
MIPCI-APCI0019-P002A-75P-KE
  round 1.092 hole 1.092 unplated: (-10,0)
  round 1.6 hole 1.6 unplated: (10,0)
  rect 0.305x1.549 smd: 1(-9.25,5.275) 2(-9,-2.275) 3(-8.75,5.275) 4(-8.5,-2.275) 5(-8.25,5.275) 6(-8,-2.275) 7(-7.75,5.275) 8(-7.5,-2.275) 9(-7.25,5.275) 10(-7,-2.275) 11(-6.75,5.275) 12(-6.5,-2.275) 13(-6.25,5.275) 14(-6,-2.275) 15(-5.75,5.275) 16(-5.5,-2.275) 17(-5.25,5.275) 18(-5,-2.275) 19(-4.75,5.275) 20(-4.5,-2.275) 21(-4.25,5.275) 22(-4,-2.275) 23(-3.75,5.275) 32(-1.5,-2.275) 33(-1.25,5.275) 34(-1,-2.275) 35(-0.75,5.275) 36(-0.5,-2.275) 37(-0.25,5.275) 38(0,-2.275) 39(0.25,5.275) 40(0.5,-2.275) 41(0.75,5.275) 42(1,-2.275) 43(1.25,5.275) 44(1.5,-2.275) 45(1.75,5.275) 46(2,-2.275) 47(2.25,5.275) 48(2.5,-2.275) 49(2.75,5.275) 50(3,-2.275) 51(3.25,5.275) 52(3.5,-2.275) 53(3.75,5.275) 54(4,-2.275) 55(4.25,5.275) 56(4.5,-2.275) 57(4.75,5.275) 58(5,-2.275) 59(5.25,5.275) 60(5.5,-2.275) 61(5.75,5.275) 62(6,-2.275) 63(6.25,5.275) 64(6.5,-2.275) 65(6.75,5.275) 66(7,-2.275) 67(7.25,5.275) 68(7.5,-2.275) 69(7.75,5.275) 70(8,-2.275) 71(8.25,5.275) 72(8.5,-2.275) 73(8.75,5.275) 74(9,-2.275) 75(9.25,5.275)
  rect 1.194x2.743 smd: 76(-10.35,4.5) 77(10.35,4.5)
MSOP8-4_9-65
  rect 0.406x1.448 smd: 1(-0.975,-2.325) 2(-0.325,-2.325) 3(0.325,-2.325) 4(0.975,-2.325) 5(0.975,2.325) 6(0.325,2.325) 7(-0.325,2.325) 8(-0.975,2.325)
PG-TSDSON-8-8P-R
  rect 0.787x0.33 smd: 1(1.5,-0.975) 2(1.5,-0.325) 3(1.5,0.325) 4(1.5,0.975)
  custom 0.573x0.573 smd: 5(-0.72,0)
  rect 0.66x0.33 smd: 6(-1.575,0.325) 7(-1.575,-0.325) 8(-1.575,-0.975)
PHJK-2SJ3061-021111F-7P
  oval 0.991x1.905 hole 0.61x1.499: 1(-4.5,7) 2(4.3,2.25) 3(-4.5,0) 4(4.3,0) 5(4.3,7) 6(4.3,4.45) 7(-4.5,3.7)
POWER-FDMC7678-5P
  rect 0.711x0.432 smd: 1(1.4,-0.975) 2(1.4,-0.325) 3(1.4,0.325) 4(1.4,0.975)
  custom 0.538x0.538 smd: 5(-0.675,0)
PVQFN20-3_5X3_5-5-25P
  rect 0.279x0.838 smd: 1(-1,-1.725) 2(-0.5,-1.725) 3(0,-1.725) 4(0.5,-1.725) 5(1,-1.725) 11(1,1.725) 12(0.5,1.725) 13(0,1.725) 14(-0.5,1.725) 15(-1,1.725)
  rect 0.838x0.279 smd: 6(1.725,-1) 7(1.725,-0.5) 8(1.725,0) 9(1.725,0.5) 10(1.725,1) 16(-1.725,1) 17(-1.725,0.5) 18(-1.725,0) 19(-1.725,-0.5) 20(-1.725,-1)
  rect 2.057x2.057 smd: 21(0,0)
  round 0.61 hole 0.305: 22(-0.5,-0.5) 23(0.5,-0.5) 24(0.5,0.5) 25(-0.5,0.5)
QFN16-3X3-5-17P-WM9001
  rect 0.965x0.305 smd: 1(-1.612,0.75) 2(-1.612,0.25) 3(-1.612,-0.25) 4(-1.612,-0.75) 9(1.612,-0.75) 10(1.612,-0.25) 11(1.612,0.25) 12(1.612,0.75)
  rect 0.305x0.965 smd: 5(-0.75,-1.612) 6(-0.25,-1.612) 7(0.25,-1.612) 8(0.75,-1.612) 13(0.75,1.612) 14(0.25,1.612) 15(-0.25,1.612) 16(-0.75,1.612)
  rect 1.702x1.702 smd: 17(0,0)
